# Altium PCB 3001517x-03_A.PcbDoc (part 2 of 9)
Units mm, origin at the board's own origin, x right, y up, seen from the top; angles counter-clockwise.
Board outline 100 x 72 mm, 10 copper layers (Top, GND_2, Signal_3, Signal_4, PWR_5, GND_6, Signal_7, Signal_8, GND_9, Bottom), stack 1.6 mm thick; 602 components, 497 nets, 2372 pads, 1602 vias.
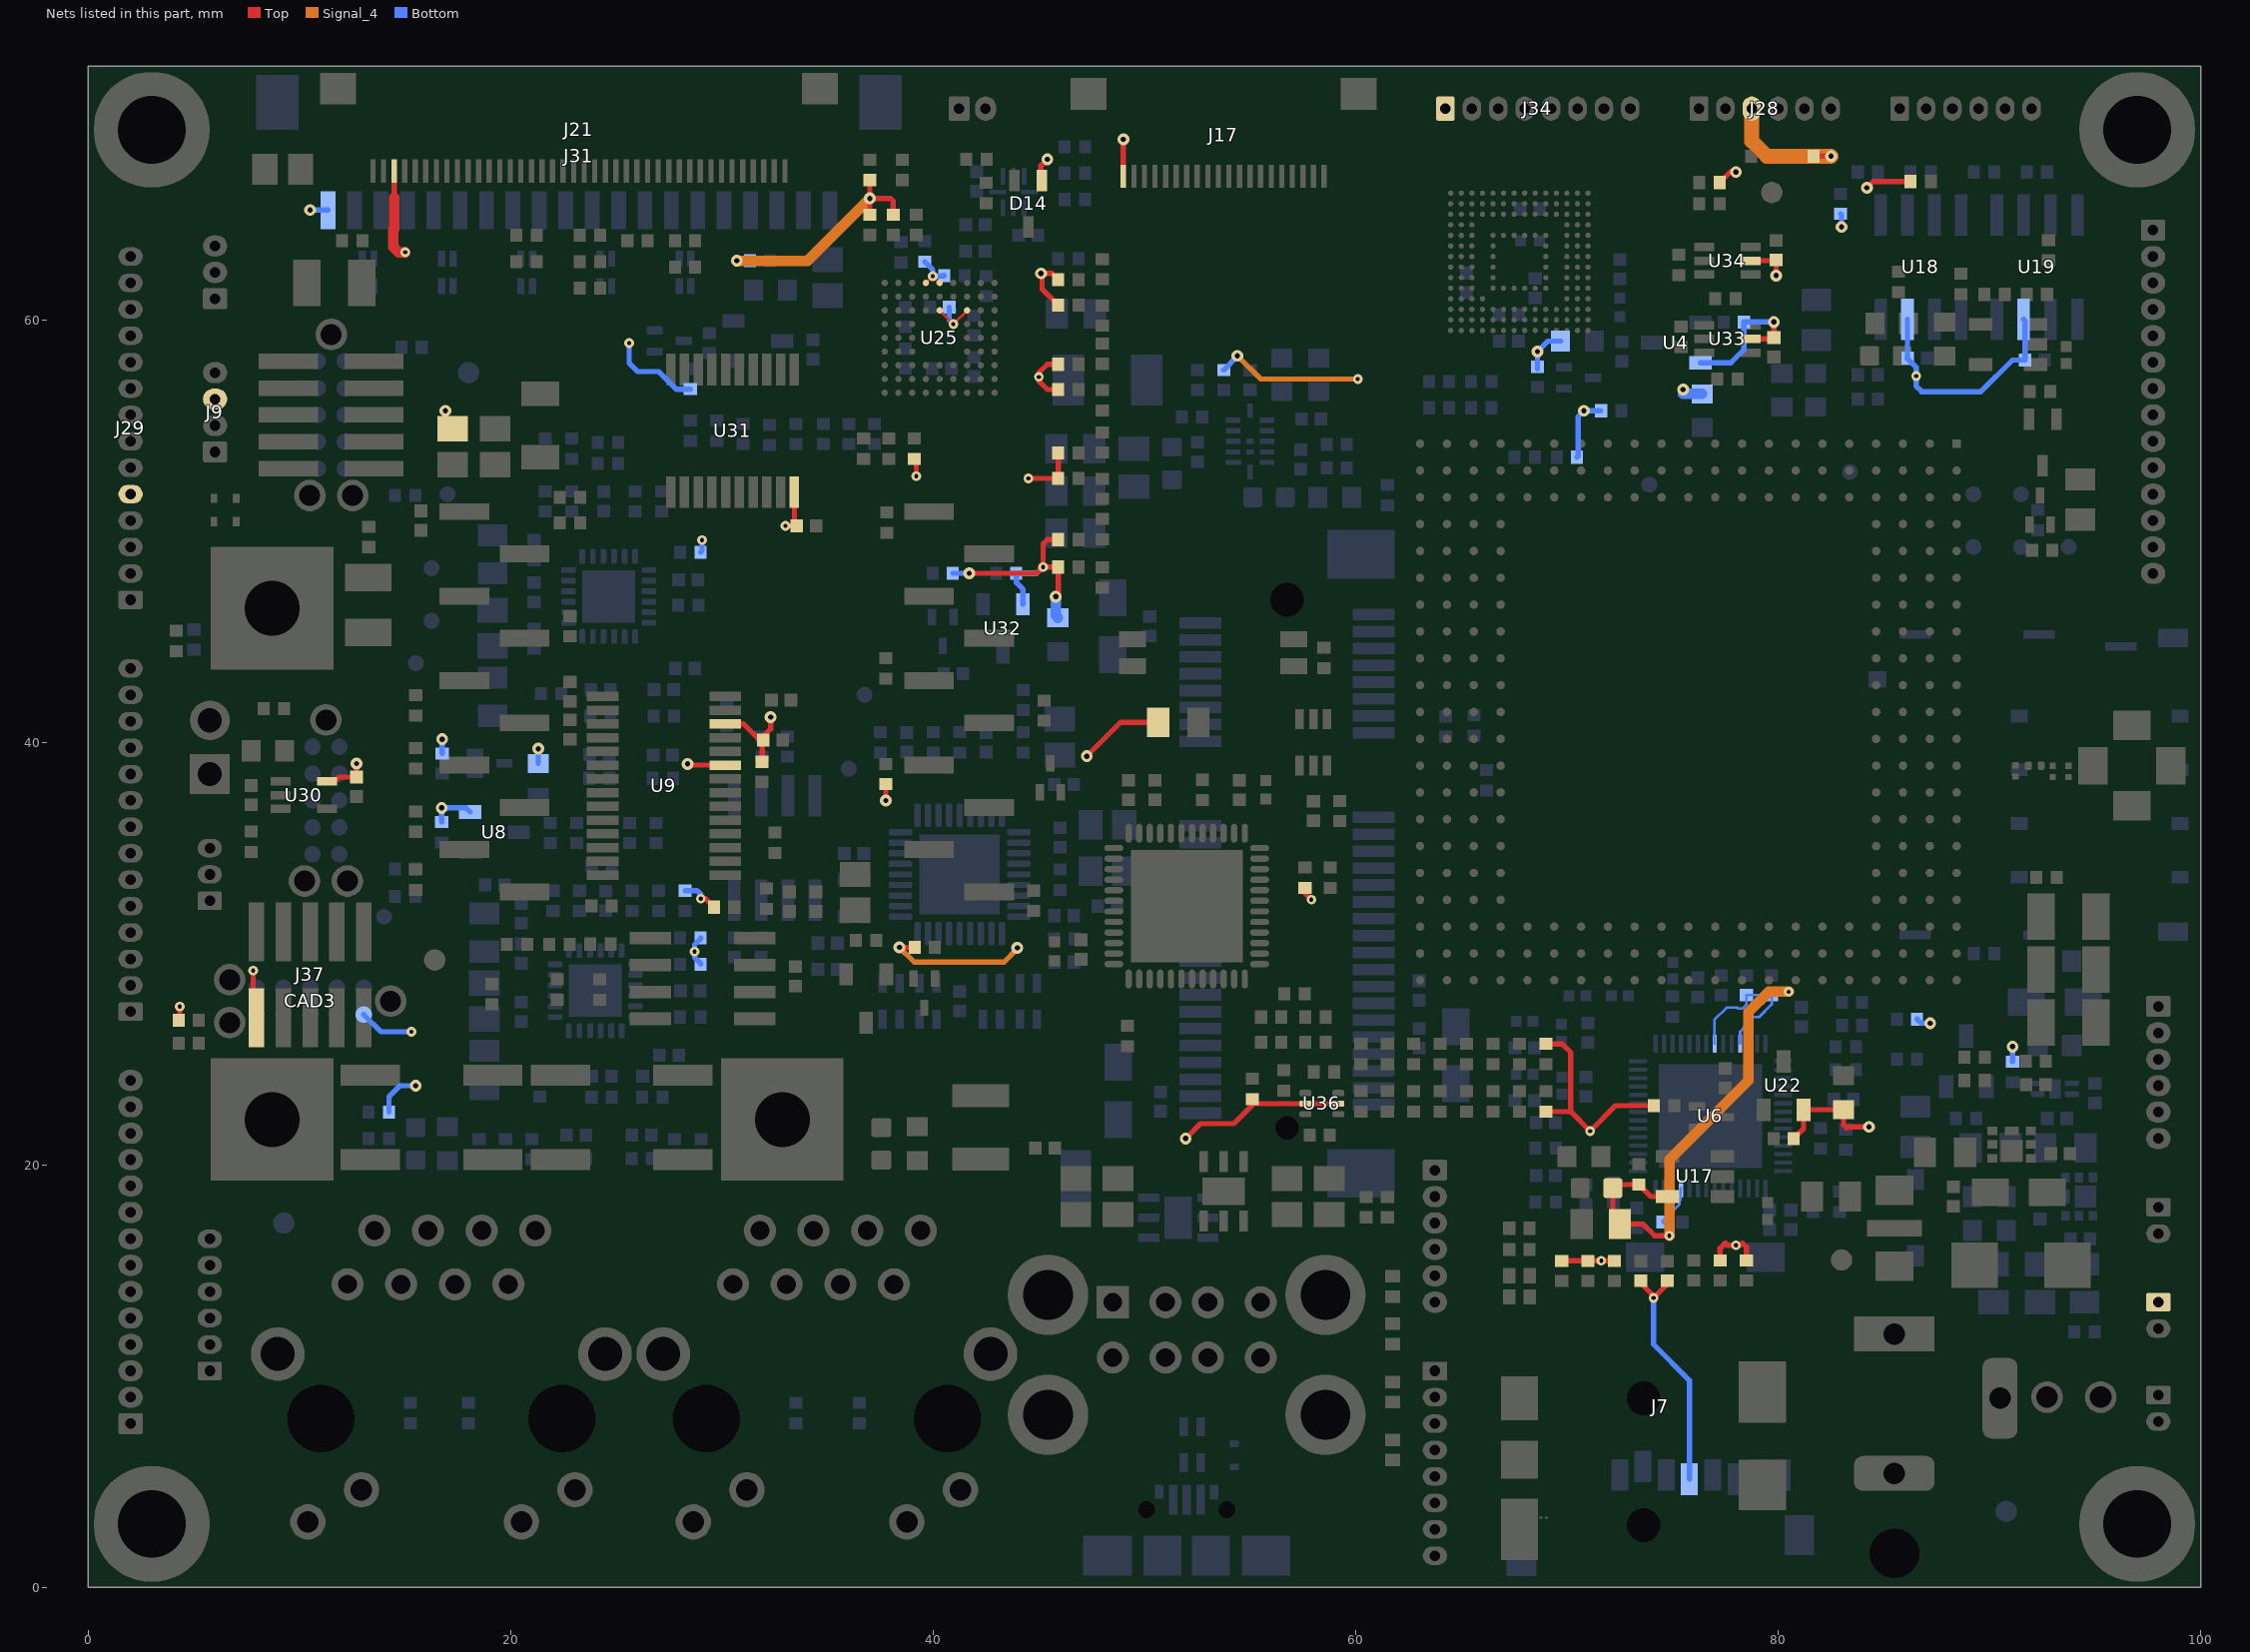
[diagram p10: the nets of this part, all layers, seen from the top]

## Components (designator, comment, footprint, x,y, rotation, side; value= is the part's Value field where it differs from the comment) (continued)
U32 "SI2323DS-T1-E3" SOT95P240X110_GSD-3N 43.299,45.389 r0 bottom
U33 "NLASB3157DFT2G" SOT65P210X110-6N 77.6,59.1 r270 top
U34 "NLASB3157DFT2G" SOT65P210X110-6N 77.6,62.8 r270 top
U35 "SI2323DS-T1-E3" SOT95P240X110_GSD-3N 31.7,59 r90 bottom
U36 "DMG1026UV-7" SOTFL50P160X60-6N 58.4,22.9 r0 top
X2 "24MHz" XTAL_C3E-3427 48.25,35 r90 bottom

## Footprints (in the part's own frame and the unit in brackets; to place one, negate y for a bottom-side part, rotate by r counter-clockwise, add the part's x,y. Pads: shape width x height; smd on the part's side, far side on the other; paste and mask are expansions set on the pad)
AMPHENOL_908-22101 [mil]
  rect 70x55 smd mask+3.94: 1(0,-72.5) 3(0,72.5)
  rect 55x70 smd mask+3.94: 2(-75,0) 4(75,0)
  Top pour cut-out: -48,-45 -48,45 48,45 48,-45
  silkscreen extent 50,-110 60,-100, body extent -85,-85 85,85, height 142
BGA72C65P9X9_700X700X112 [mm] "72-ball  BGA, 7x7mm"
  round 0.3 smd paste+0 mask+0: A1(-2.6,2.6) A2(-1.95,2.6) A3(-1.3,2.6) A4(-0.65,2.6) A5(0,2.6) A6(0.65,2.6) A7(1.3,2.6) A8(1.95,2.6) A9(2.6,2.6) B1(-2.6,1.95) B2(-1.95,1.95) B3(-1.3,1.95) B4(-0.65,1.95) B5(0,1.95) B6(0.65,1.95) B7(1.3,1.95) B8(1.95,1.95) B9(2.6,1.95) C1(-2.6,1.3) C2(-1.95,1.3) C3(-1.3,1.3) C4(-0.65,1.3) C5(0,1.3) C6(0.65,1.3) C7(1.3,1.3) C8(1.95,1.3) C9(2.6,1.3) D1(-2.6,0.65) D2(-1.95,0.65) D3(-1.3,0.65) D7(1.3,0.65) D8(1.95,0.65) D9(2.6,0.65) E1(-2.6,0) E2(-1.95,0) E3(-1.3,0) E7(1.3,0) E8(1.95,0) E9(2.6,0) F1(-2.6,-0.65) F2(-1.95,-0.65) F3(-1.3,-0.65) F7(1.3,-0.65) F8(1.95,-0.65) F9(2.6,-0.65) G1(-2.6,-1.3) G2(-1.95,-1.3) G3(-1.3,-1.3) G4(-0.65,-1.3) G5(0,-1.3) G6(0.65,-1.3) G7(1.3,-1.3) G8(1.95,-1.3) G9(2.6,-1.3) H1(-2.6,-1.95) H2(-1.95,-1.95) H3(-1.3,-1.95) H4(-0.65,-1.95) H5(0,-1.95) H6(0.65,-1.95) H7(1.3,-1.95) H8(1.95,-1.95) H9(2.6,-1.95) J1(-2.6,-2.6) J2(-1.95,-2.6) J3(-1.3,-2.6) J4(-0.65,-2.6) J5(0,-2.6) J6(0.65,-2.6) J7(1.3,-2.6) J8(1.95,-2.6) J9(2.6,-2.6)
  silkscreen extent -3.9,-3.5 3.5,3.9, body extent -3.5,-3.5 3.5,3.5, height 1.12
BGA153C50P14X14_1150X1300X100 [mm] "Sandisk eMMC"
  round 0.25 smd mask+0: A1(-3.25,3.25) A2(-2.75,3.25) A3(-2.25,3.25) A4(-1.75,3.25) A5(-1.25,3.25) A6(-0.75,3.25) A7(-0.25,3.25) A8(0.25,3.25) A9(0.75,3.25) A10(1.25,3.25) A11(1.75,3.25) A12(2.25,3.25) A13(2.75,3.25) A14(3.25,3.25) B1(-3.25,2.75) B2(-2.75,2.75) B3(-2.25,2.75) B4(-1.75,2.75) B5(-1.25,2.75) B6(-0.75,2.75) B7(-0.25,2.75) B8(0.25,2.75) B9(0.75,2.75) B10(1.25,2.75) B11(1.75,2.75) B12(2.25,2.75) B13(2.75,2.75) B14(3.25,2.75) C1(-3.25,2.25) C2(-2.75,2.25) C3(-2.25,2.25) C4(-1.75,2.25) C5(-1.25,2.25) C6(-0.75,2.25) C7(-0.25,2.25) C8(0.25,2.25) C9(0.75,2.25) C10(1.25,2.25) C11(1.75,2.25) C12(2.25,2.25) C13(2.75,2.25) C14(3.25,2.25) D1(-3.25,1.75) D2(-2.75,1.75) D3(-2.25,1.75) D4(-1.75,1.75) D12(2.25,1.75) D13(2.75,1.75) D14(3.25,1.75) E1(-3.25,1.25) E2(-2.75,1.25) E3(-2.25,1.25) E5(-1.25,1.25) E6(-0.75,1.25) E7(-0.25,1.25) E8(0.25,1.25) E9(0.75,1.25) E10(1.25,1.25) E12(2.25,1.25) E13(2.75,1.25) E14(3.25,1.25) F1(-3.25,0.75) F2(-2.75,0.75) F3(-2.25,0.75) F5(-1.25,0.75) F10(1.25,0.75) F12(2.25,0.75) F13(2.75,0.75) F14(3.25,0.75) G1(-3.25,0.25) G2(-2.75,0.25) G3(-2.25,0.25) G5(-1.25,0.25) G10(1.25,0.25) G12(2.25,0.25) G13(2.75,0.25) G14(3.25,0.25) H1(-3.25,-0.25) H2(-2.75,-0.25) H3(-2.25,-0.25) H5(-1.25,-0.25) H10(1.25,-0.25) H12(2.25,-0.25) H13(2.75,-0.25) H14(3.25,-0.25) J1(-3.25,-0.75) J2(-2.75,-0.75) J3(-2.25,-0.75) J5(-1.25,-0.75) J10(1.25,-0.75) J12(2.25,-0.75) J13(2.75,-0.75) J14(3.25,-0.75) K1(-3.25,-1.25) K2(-2.75,-1.25) K3(-2.25,-1.25) K5(-1.25,-1.25) K6(-0.75,-1.25) K7(-0.25,-1.25) K8(0.25,-1.25) K9(0.75,-1.25) K10(1.25,-1.25) K12(2.25,-1.25) K13(2.75,-1.25) K14(3.25,-1.25) L1(-3.25,-1.75) L2(-2.75,-1.75) L3(-2.25,-1.75) L12(2.25,-1.75) L13(2.75,-1.75) L14(3.25,-1.75) M1(-3.25,-2.25) M2(-2.75,-2.25) M3(-2.25,-2.25) M4(-1.75,-2.25) M5(-1.25,-2.25) M6(-0.75,-2.25) M7(-0.25,-2.25) M8(0.25,-2.25) M9(0.75,-2.25) M10(1.25,-2.25) M11(1.75,-2.25) M12(2.25,-2.25) M13(2.75,-2.25) M14(3.25,-2.25) N1(-3.25,-2.75) N2(-2.75,-2.75) N3(-2.25,-2.75) N4(-1.75,-2.75) N5(-1.25,-2.75) N6(-0.75,-2.75) N7(-0.25,-2.75) N8(0.25,-2.75) N9(0.75,-2.75) N10(1.25,-2.75) N11(1.75,-2.75) N12(2.25,-2.75) N13(2.75,-2.75) N14(3.25,-2.75) P1(-3.25,-3.25) P2(-2.75,-3.25) P3(-2.25,-3.25) P4(-1.75,-3.25) P5(-1.25,-3.25) P6(-0.75,-3.25) P7(-0.25,-3.25) P8(0.25,-3.25) P9(0.75,-3.25) P10(1.25,-3.25) P11(1.75,-3.25) P12(2.25,-3.25) P13(2.75,-3.25) P14(3.25,-3.25)
  silkscreen extent -6.3,6.1 -6.1,6.3, body extent -5.8,-6.55 5.8,6.55, height 1.01
CAPC0603X33AL [mil]
  rect 12x12 smd mask+2: 1(-10.5,0) 2(10.5,0)
  body extent -12,-6 12,6, height 13
CAPC1005X55AL [mm]
  rect 0.52x0.52 smd mask+0.051: 1(-0.44,0) 2(0.44,0)
  body extent -0.5,-0.25 0.5,0.25, height 0.55
CAPC1005X55L [mm]
  rect 0.52x0.52 smd mask+0.05: 1(-0.4,0) 2(0.4,0)
  body extent -0.5,-0.25 0.5,0.25, height 0.55
CAPC1005X55N#1 [mm]
  rect 0.6x0.62 smd: 1(-0.46,0) 2(0.46,0)
  body extent -0.5,-0.25 0.5,0.25, height 0.55
CAPC1005X55N#2 [mm]
  rect 0.6x0.62 smd mask+0.05: 1(-0.46,0) 2(0.46,0)
  body extent -0.5,-0.25 0.5,0.25, height 0.55
CAPC1608X90N#1 [mm] "0603"
  rect 0.95x1 smd: 1(-0.8,0) 2(0.8,0)
  body extent -0.87,-0.47 0.87,0.47, height 0.9
CAPC1608X90N#2 [mm] "0603"
  rrect22% 0.89x0.93 smd: 1(-0.77,0) 2(0.77,0)
  body extent -0.8,-0.4 0.8,0.4, height 0.9
CAPC2013X135N [mm] "0805, 1.35mm max height"
  rect 1.05x1.4 smd: 1(-0.9,0) 2(0.9,0)
  body extent -1.1,-0.72 1.1,0.72, height 1.35
CAPC2013X145N [mm] "0805, 1.45mm max height"
  rect 1.15x1.45 smd: 1(-0.9,0) 2(0.9,0)
  body extent -1.1,-0.72 1.1,0.72, height 1.45
CAPC3216X190N [mm]
  rect 1.15x1.8 smd: 1(-1.5,0) 2(1.5,0)
  body extent -1.7,-0.9 1.7,0.9, height 1.9
CAPMP3216X120N [mm]
  rect 1.75x1.3 smd: 1(-1.35,0) 2(1.35,0)
  body extent -1.7,-0.9 1.7,0.9, height 1.21
CC6UL_LGA [mm]
  rect 0.4x0.4 smd paste-0.4: A1(-12.64,12.7)
  round 0.4 smd paste+0.3 mask+0.05: A2(-11.37,12.7) A3(-10.1,12.7) A4(-8.83,12.7) A5(-7.56,12.7) A6(-6.29,12.7) A7(-5.02,12.7) A8(-3.75,12.7) A9(-2.48,12.7) A10(-1.21,12.7) A11(0.06,12.7) A12(1.33,12.7) A13(2.6,12.7) A14(3.87,12.7) A15(5.14,12.7) A16(6.41,12.7) A17(7.68,12.7) A18(8.95,12.7) A19(10.22,12.7) A20(11.49,12.7) A21(12.76,12.7) AA1(-12.64,-12.7) AA2(-11.37,-12.7) AA3(-10.1,-12.7) AA4(-8.83,-12.7) AA5(-7.56,-12.7) AA6(-6.29,-12.7) AA7(-5.02,-12.7) AA8(-3.75,-12.7) AA9(-2.48,-12.7) AA10(-1.21,-12.7) AA11(0.06,-12.7) AA12(1.33,-12.7) AA13(2.6,-12.7) AA14(3.87,-12.7) AA15(5.14,-12.7) AA16(6.41,-12.7) AA17(7.68,-12.7) AA18(8.95,-12.7) AA19(10.22,-12.7) AA20(11.49,-12.7) AA21(12.76,-12.7) B1(-12.64,11.43) B2(-11.37,11.43) B3(-10.1,11.43) B4(-8.83,11.43) B5(-7.56,11.43) B6(-6.29,11.43) B7(-5.02,11.43) B8(-3.75,11.43) B9(-2.48,11.43) B10(-1.21,11.43) B11(0.06,11.43) B12(1.33,11.43) B13(2.6,11.43) B14(3.87,11.43) B15(5.14,11.43) B16(6.41,11.43) B17(7.68,11.43) B18(8.95,11.43) B19(10.22,11.43) B20(11.49,11.43) B21(12.76,11.43) C1(-12.64,10.16) C2(-11.37,10.16) C3(-10.1,10.16) C4(-8.83,10.16) C5(-7.56,10.16) C6(-6.29,10.16) C7(-5.02,10.16) C8(-3.75,10.16) C9(-2.48,10.16) C10(-1.21,10.16) C11(0.06,10.16) C12(1.33,10.16) C13(2.6,10.16) C14(3.87,10.16) C15(5.14,10.16) C16(6.41,10.16) C17(7.68,10.16) C18(8.95,10.16) C19(10.22,10.16) C20(11.49,10.16) C21(12.76,10.16) D1(-12.64,8.89) D2(-11.37,8.89) D3(-10.1,8.89) D4(-8.83,8.89) D5(-7.56,8.89) D6(-6.29,8.89) D7(-5.02,8.89) D8(-3.75,8.89) D9(-2.48,8.89) D10(-1.21,8.89) D11(0.06,8.89) D12(1.33,8.89) D13(2.6,8.89) D14(3.87,8.89) D15(5.14,8.89) D16(6.41,8.89) D17(7.68,8.89) D18(8.95,8.89) D19(10.22,8.89) D20(11.49,8.89) D21(12.76,8.89) E1(-12.64,7.62) E2(-11.37,7.62) E3(-10.1,7.62) E19(10.22,7.62) E20(11.49,7.62) E21(12.76,7.62) F1(-12.64,6.35) F2(-11.37,6.35) F3(-10.1,6.35) F19(10.22,6.35) F20(11.49,6.35) F21(12.76,6.35) G1(-12.64,5.08) G2(-11.37,5.08) G3(-10.1,5.08) G19(10.22,5.08) G20(11.49,5.08) G21(12.76,5.08) H1(-12.64,3.81) H2(-11.37,3.81) H3(-10.1,3.81) H19(10.22,3.81) H20(11.49,3.81) H21(12.76,3.81) J1(-12.64,2.54) J2(-11.37,2.54) J3(-10.1,2.54) J19(10.22,2.54) J20(11.49,2.54) J21(12.76,2.54) K1(-12.64,1.27) K2(-11.37,1.27) K3(-10.1,1.27) K19(10.22,1.27) K20(11.49,1.27) K21(12.76,1.27) L1(-12.64,0) L2(-11.37,0) L3(-10.1,0) L19(10.22,0) L20(11.49,0) L21(12.76,0) M1(-12.64,-1.27) M2(-11.37,-1.27) M3(-10.1,-1.27) M19(10.22,-1.27) M20(11.49,-1.27) M21(12.76,-1.27) N1(-12.64,-2.54) N2(-11.37,-2.54) N3(-10.1,-2.54) N19(10.22,-2.54) N20(11.49,-2.54) N21(12.76,-2.54) P1(-12.64,-3.81) P2(-11.37,-3.81) P3(-10.1,-3.81) P19(10.22,-3.81) P20(11.49,-3.81) P21(12.76,-3.81) R1(-12.64,-5.08) R2(-11.37,-5.08) R3(-10.1,-5.08) R19(10.22,-5.08) R20(11.49,-5.08) R21(12.76,-5.08) T1(-12.64,-6.35) T2(-11.37,-6.35) T3(-10.1,-6.35) T19(10.22,-6.35) T20(11.49,-6.35) T21(12.76,-6.35) U1(-12.64,-7.62) U2(-11.37,-7.62) U3(-10.1,-7.62) U19(10.22,-7.62) U20(11.49,-7.62) U21(12.76,-7.62) V1(-12.64,-8.89) V2(-11.37,-8.89) V3(-10.1,-8.89) V4(-8.83,-8.89) V5(-7.56,-8.89) V6(-6.29,-8.89) V7(-5.02,-8.89) V8(-3.75,-8.89) V9(-2.48,-8.89) V10(-1.21,-8.89) V11(0.06,-8.89) V12(1.33,-8.89) V13(2.6,-8.89) V14(3.87,-8.89) V15(5.14,-8.89) V16(6.41,-8.89) V17(7.68,-8.89) V18(8.95,-8.89) V19(10.22,-8.89) V20(11.49,-8.89) V21(12.76,-8.89) W1(-12.64,-10.16) W2(-11.37,-10.16) W3(-10.1,-10.16) W4(-8.83,-10.16) W5(-7.56,-10.16) W6(-6.29,-10.16) W7(-5.02,-10.16) W8(-3.75,-10.16) W9(-2.48,-10.16) W10(-1.21,-10.16) W11(0.06,-10.16) W12(1.33,-10.16) W13(2.6,-10.16) W14(3.87,-10.16) W15(5.14,-10.16) W16(6.41,-10.16) W17(7.68,-10.16) W18(8.95,-10.16) W19(10.22,-10.16) W20(11.49,-10.16) W21(12.76,-10.16) Y1(-12.64,-11.43) Y2(-11.37,-11.43) Y3(-10.1,-11.43) Y4(-8.83,-11.43) Y5(-7.56,-11.43) Y6(-6.29,-11.43) Y7(-5.02,-11.43) Y8(-3.75,-11.43) Y9(-2.48,-11.43) Y10(-1.21,-11.43) Y11(0.06,-11.43) Y12(1.33,-11.43) Y13(2.6,-11.43) Y14(3.87,-11.43) Y15(5.14,-11.43) Y16(6.41,-11.43) Y17(7.68,-11.43) Y18(8.95,-11.43) Y19(10.22,-11.43) Y20(11.49,-11.43) Y21(12.76,-11.43)
  body extent -14.44,-14.5 14.56,17.36, height 4.35
conn_CSCD443CCS011B00G [mil] "Bobbintron : CSCD443CCS011B00G"
  rect 65x150 hole 40 slot 126 at 90 deg: 1(0,0)
  rrect50% 65x150 / inner rect 65x150 / far side rrect50% 65x150 hole 40 slot 126 at 90 deg: 2(-260,0)
  rrect50% 150x65 / inner rect 150x65 / far side rrect50% 150x65 hole 40 slot 126 at 0 deg: 3(-120,-197.01)
  round 0 hole 93 unplated: 4(-409,0)
  body extent -571,-207 20,177, height 433
CUI_SJ1-3515-SMT [mm]
  rect 2.9x1.75 smd: 1(-3.25,5.75)
  rect 2.9x2.25 smd: 2(3.25,-5.75)
  rect 2.1x1.75 smd: 3(2.95,5.75)
  rect 2.4x2.25 smd: 4(-1.15,-5.75)
  rect 1.8x1.75 smd: 5(0.05,5.75)
  round 0 hole 1.6 unplated: MT1(-3.05,-0.125) MT2(2.95,-0.125)
  body extent -9.05,-6.12 5.95,5.88, height 5
DFN200X200X80-6N [mm]
  rect 0.47x0.4 smd mask+0.05: 1(-0.91,0.65) 2(-0.91,0) 3(-0.91,-0.65) 4(0.91,-0.65) 5(0.91,0) 6(0.91,0.65)
  rect 1.05x1 smd mask+0: 7(0,0.3)
  rect 0.66x0.4 smd mask+0.05: 8(0,-0.65)
  silkscreen extent -0.87,-1.62 -0.63,-1.38, body extent -1,-1 1,1, height 0.8
DIOM5436X244N [mm]
  rect 2.2x2.15 smd: A(-2.2,0) K(2.2,0)
  body extent -2.8,-1.97 2.8,1.97, height 2.44
FCI_68002-102HLF [mil]
  rect 74x74 hole 45: 1(0,0)
  round 74 hole 45: 2(100,0)
  body extent -51,-46 149,49, height 330
fiducial_40mil_round [mil]
  round 40 smd paste-40 mask+20: 1(0,0)
  Top pour cut-out: -40,0 -36.96,15.31 -28.28,28.28 -15.31,36.96 0,40 0,40 15.31,36.96 28.28,28.28 36.96,15.31 40,0 40,0 36.96,-15.31 28.28,-28.28 15.31,-36.96 0,-40 0,-40 -15.31,-36.96 -28.28,-28.28 -36.96,-15.31 -40,0
FIL_DLP11S [mm]
  rect 0.75x0.35 smd: 1(-0.65,-0.275) 2(0.65,-0.275) 3(0.65,0.275) 4(-0.65,0.275)
  silkscreen extent -0.88,-1.15 -0.73,-1, body extent -0.67,-0.55 0.68,0.55, height 0.92
FIL_DLW21H [mm]
  rect 0.9x0.4 smd: 1(-0.85,-0.4) 2(0.85,-0.4) 3(0.85,0.4) 4(-0.85,0.4)
  body extent -1.1,-0.7 1.1,0.7, height 1
FIL_ELKEA [mm]
  rect 1.4x1.8 smd: 1(-1.8,0) 3(1.8,0)
  rect 0.8x2.6 smd: 2(0,0)
  body extent -1.6,-0.9 1.6,0.9, height 2.2
FOXCONN_AS0B221-S68Q-7H [mm]
  rect 0.55x2 smd: 1(0.7,-4.1) 2(1.1,4.1) 3(1.5,-4.1) 4(1.9,4.1) 5(2.3,-4.1) 6(2.7,4.1) 7(3.1,-4.1) 8(3.5,4.1) 9(3.9,-4.1) 10(4.3,4.1) 11(4.7,-4.1) 12(5.1,4.1) 13(5.5,-4.1) 14(5.9,4.1) 15(6.3,-4.1) 16(6.7,4.1) 17(10.3,-4.1) 18(10.7,4.1) 19(11.1,-4.1) 20(11.5,4.1) 21(11.9,-4.1) 22(12.3,4.1) 23(12.7,-4.1) 24(13.1,4.1) 25(13.5,-4.1) 26(13.9,4.1) 27(14.3,-4.1) 28(14.7,4.1) 29(15.1,-4.1) 30(15.5,4.1) 31(15.9,-4.1) 32(16.3,4.1) 33(16.7,-4.1) 34(17.1,4.1) 35(17.5,-4.1) 36(17.9,4.1) 37(18.3,-4.1) 38(18.7,4.1) 39(19.1,-4.1) 40(19.5,4.1) 41(19.9,-4.1) 42(20.3,4.1) 43(20.7,-4.1) 44(21.1,4.1) 45(21.5,-4.1) 46(21.9,4.1) 47(22.3,-4.1) 48(22.7,4.1) 49(23.1,-4.1) 50(23.5,4.1) 51(23.9,-4.1) 52(24.3,4.1)
  round 0 hole 1.6 unplated: H1(0,0)
  round 0 hole 1.1 unplated: H2(25,0)
  rect 2.3x3.2 smd: MT1(-2.15,-3.5) MT2(27.15,-3.5)
  body extent -2.4,-4.75 27.4,4.75, height 6.8
HIROSE_DF14A-20P-1.25H [mm]
  rect 0.7x1.8 smd: 1(11.875,-2.55) 2(10.625,-2.55) 3(9.375,-2.55) 4(8.125,-2.55) 5(6.875,-2.55) 6(5.625,-2.55) 7(4.375,-2.55) 8(3.125,-2.55) 9(1.875,-2.55) 10(0.625,-2.55) 11(-0.625,-2.55) 12(-1.875,-2.55) 13(-3.125,-2.55) 14(-4.375,-2.55) 15(-5.625,-2.55) 16(-6.875,-2.55) 17(-8.125,-2.55) 18(-9.375,-2.55) 19(-10.625,-2.55) 20(-11.875,-2.55)
  rect 2x2.6 smd: MT1(14.275,2.55) MT21(-14.275,2.55)
  body extent -14.97,-3.02 14.98,3.68, height 2.49
INDC0603X33N [mm]
  rrect48% 0.33x0.4 smd: 1(-0.3,0) 2(0.3,0)
  silkscreen extent -0.3,-0.38 0.3,0.38, body extent -0.3,-0.15 0.3,0.15, height 0.33
INDC1005X60N [mm]
  rect 0.59x0.72 smd: 1(-0.48,0) 2(0.48,0)
  body extent -0.55,-0.35 0.55,0.35, height 0.6
INDC2013X110N [mm]
  rect 1.2x1.45 smd: 1(-0.85,0) 2(0.85,0)
  body extent -1.1,-0.72 1.1,0.72, height 1.1
INDM_SRP4020TA [mm]
  rect 1.5x2.4 smd: 1(-1.85,0) 2(1.85,0)
  body extent -2.2,-2.1 2.2,2.1, height 1.91
KYCON_KMMX-ABSMT5 [mm]
  rect 0.4x0.7 smd mask+0.058: 1(-1.3,3)
  rect 0.4x1.4 smd: 2(-0.65,2.65) 3(0,2.65) 4(0.65,2.65)
  rect 0.4x0.65 smd mask+0.058: 5(1.3,3.025)
  rect 2.3x1.9 smd: 6(-3.75,0) 9(3.75,0)
  rect 1.8x1.9 smd: 7(-1.15,0) 8(1.15,0)
  round 0 hole 0.813 unplated: 10(-1.9,2.18) 11(1.9,2.18)
  Top region: 1.1,2.7 1.1,1.95 1.275,1.95 1.275,2.18 1.278,2.235 1.28,2.258 1.282,2.278 1.285,2.29 1.288,2.305 1.29,2.315 1.292,2.328 1.3,2.355 1.308,2.378 1.315,2.4 1.32,2.412 1.335,2.448 1.34,2.458 1.342,2.462 1.345,2.468 1.358,2.49 1.372,2.515 1.388,2.538 1.4,2.555 1.418,2.578 1.435,2.598 1.482,2.645 1.5,2.66 1.5,2.7
  Top region: -1.1,2.7 -1.1,1.95 -1.275,1.95 -1.275,2.18 -1.278,2.235 -1.28,2.258 -1.282,2.278 -1.285,2.29 -1.288,2.305 -1.29,2.315 -1.292,2.328 -1.3,2.355 -1.308,2.378 -1.315,2.4 -1.32,2.412 -1.335,2.448 -1.34,2.458 -1.342,2.462 -1.345,2.468 -1.358,2.49 -1.372,2.515 -1.388,2.538 -1.4,2.555 -1.418,2.578 -1.435,2.598 -1.482,2.645 -1.5,2.66 -1.5,2.7
  body extent -4.4,-2.72 4.4,2.88, height 2.78
KYCON_KUSBX-AS2N [mil]
  rect 60x60 hole 35: A1(0,0)
  round 60 hole 35: A2(98.43,0) A3(177.17,0) A4(275.59,0) B1(0,-103.15) B2(98.43,-103.15) B3(177.17,-103.15) B4(275.59,-103.15)
  round 150 hole 93: SH1(-120.87,-209.84) SH2(-120.87,13.78) SH3(396.46,-209.84) SH4(396.46,13.78)
  body extent -171,-633 446,56, height 634
LABEL_10x10 [mm]
  silkscreen extent -5.08,-5.08 5.08,5.08
LEDM3020X130N [mm]
  rect 1.3x2.2 smd: A(-1.3,0) K(1.3,0)
  body extent -1.6,-1.1 1.6,1.1, height 1.5
MH_185_125_NP [mm]
  round 3.175 hole 3.175 unplated: 1(0,0)
  Keep-Out Layer circle w0.102: c0,0 r2.349
MOLEX_53047-0210#1 [mm]
  rrect20% 0.875x1.15 hole 0.5: 1(0,0)
  oval 0.875x1.15 hole 0.5: 2(1.25,0)
  body extent -1.52,-1.15 2.73,2.05, height 4.2
MOLEX_53047-0210#2 [mm]
  rrect20% 1x1.15 hole 0.5: 1(0,0)
  oval 1x1.15 hole 0.5: 2(1.25,0)
  body extent -1.52,-1.15 2.73,2.05, height 4.2
MOLEX_53047-0310#1 [mm]
  rrect20% 1x1.15 hole 0.5: 1(0,0)
  oval 1x1.15 hole 0.5: 2(1.25,0) 3(2.5,0)
  body extent -1.5,-1.15 4,2.05, height 4.2
MOLEX_53047-0310#2 [mm]
  rrect20% 0.875x1.15 hole 0.5: 1(0,0)
  oval 0.875x1.15 hole 0.5: 2(1.25,0) 3(2.5,0)
  body extent -1.5,-1.15 4,2.05, height 4.2
MOLEX_53047-0410 [mm]
  rrect20% 1x1.15 hole 0.5: 1(0,0)
  oval 1x1.15 hole 0.5: 2(1.25,0) 3(2.5,0) 4(3.75,0)
  body extent -1.52,-1.15 5.23,2.05, height 4.2
MOLEX_53047-0610#1 [mm]
  rrect20% 1x1.15 hole 0.5: 1(0,0)
  oval 1x1.15 hole 0.5: 2(1.25,0) 3(2.5,0) 4(3.75,0) 5(5,0) 6(6.25,0)
  body extent -1.5,-1.15 7.75,2.05, height 4.2
MOLEX_53047-0610#2 [mm]
  rrect20% 0.875x1.15 hole 0.5: 1(0,0)
  oval 0.875x1.15 hole 0.5: 2(1.25,0) 3(2.5,0) 4(3.75,0) 5(5,0) 6(6.25,0)
  body extent -1.5,-1.15 7.75,2.05, height 4.2
MOLEX_53047-0610#3 [mm]
  rrect20% 1x1.15 / inner round 0.76 / far side rrect20% 1x1.15 hole 0.5: 1(0,0)
  oval 1x1.15 / inner round 0.76 / far side oval 1x1.15 hole 0.5: 2(1.25,0)
  oval 1x1.15 hole 0.5: 3(2.5,0) 4(3.75,0) 5(5,0) 6(6.25,0)
  body extent -1.5,-1.15 7.75,2.05, height 4.2
MOLEX_53047-0810#1 [mm]
  rect 0.875x1.15 / inner rect 0.76x0.76 / far side rect 0.875x1.15 hole 0.5: 1(0,0)
  oval 0.875x1.15 / inner round 0.76 / far side oval 0.875x1.15 hole 0.5: 2(1.25,0) 3(2.5,0) 4(3.75,0) 5(5,0) 6(6.25,0) 7(7.5,0) 8(8.75,0)
  body extent -1.5,-1.15 10.25,2.05, height 4.2
MOLEX_53047-0810#2 [mm]
  rrect20% 0.875x1.15 hole 0.5: 1(0,0)
  oval 0.875x1.15 hole 0.5: 2(1.25,0) 3(2.5,0) 4(3.75,0) 5(5,0) 6(6.25,0) 7(7.5,0) 8(8.75,0)
  body extent -1.5,-1.15 10.25,2.05, height 4.2
MOLEX_53047-1410#1 [mm]
  rrect20% 1x1.15 hole 0.5: 1(0,0)
  oval 1x1.15 hole 0.5: 2(1.25,0) 3(2.5,0) 4(3.75,0) 5(5,0) 6(6.25,0) 7(7.5,0) 8(8.75,0) 9(10,0) 10(11.25,0) 11(12.5,0) 12(13.75,0) 13(15,0) 14(16.25,0)
  body extent -1.5,-1.15 17.75,2.05, height 4.2
MOLEX_53047-1410#2 [mm]
  rrect20% 0.875x1.15 hole 0.5: 1(0,0)
  oval 0.875x1.15 hole 0.5: 2(1.25,0) 3(2.5,0) 4(3.75,0) 5(5,0) 6(6.25,0) 7(7.5,0) 8(8.75,0) 9(10,0) 10(11.25,0) 11(12.5,0) 12(13.75,0) 13(15,0) 14(16.25,0)
  body extent -1.5,-1.15 17.75,2.05, height 4.2
MOLEX_78727-0001 [mm]
  rect 0.8x0.6 smd: 1(0.33,4.38) 2(0.33,1.84) 3(0.33,-0.7) 4(0.33,-3.24) 5(-7.29,4.38) 6(-7.29,1.84) 7(-7.29,-0.7) 8(-7.29,-3.24)
  rect 0.85x0.8 smd: 9(-13.99,-4.98)
  rect 1.5x0.42 smd: 10(-2.47,-6.54) 12(-6.35,7.11) 13(-12.21,7.11) 14(-12.21,-7.11) 15(-6.35,-7.11)
  rect 1.4x0.87 smd: 11(0,6.95) 16(0,-6.95)
  body extent -14.53,-7.26 0.69,7.27, height 1.4
MOLEX_500873-0806 [mm]
  rect 0.8x1.5 smd: 1(0,0) 2(1.1,-0.4) 3(2.2,0) 4(3.3,0.2) 5(4.4,0) 6(5.5,0.2) 7(6.6,0) 8(7.7,0)
  rect 1.8x1.4 smd: 9(1.2,-10.3) 10(6.9,-10.3)
  rect 1.4x1.9 smd: 11(8.5,2.85) 12(-4.65,3.85)
  body extent -5.05,-10.7 8.95,4.5, height 1.87
NET_TIE_4mil [mil] "Net Tie for 4mil traces"
  rect 5x4 smd paste-5 mask-5: 1(-5,0) 2(5,0)
  Top region: -3,-2 3,-2 3,2 -3,2
NXP_XQFN8 [mm] "Quad Flat No-Lead (QFN), 0.50 mm pitch; square, 3 pin X 1 pin, 1.60 mm L X 1.60 mm W X 0.50 mm H body"
  rrect55% 0.81x0.22 smd mask+0.05: 1(-0.75,0.5) 2(-0.75,0) 3(-0.75,-0.5) 5(0.75,-0.5) 6(0.75,0) 7(0.75,0.5)
  rrect55% 0.22x0.81 smd mask+0.05: 4(0,-0.75) 8(0,0.75)
  Top keep-out region: -0.2,0.2 0.2,0.2 0.2,-0.2 -0.2,-0.2
  silkscreen extent -1.65,0.7 -1.45,0.9, body extent -0.85,-0.85 0.85,0.85, height 0.5
omron_xf2m-2015-1a [mm]
  rect 0.25x1.1 smd: 1(-4.75,1.95) 2(-4.25,1.95) 3(-3.75,1.95) 4(-3.25,1.95) 5(-2.75,1.95) 6(-2.25,1.95) 7(-1.75,1.95) 8(-1.25,1.95) 9(-0.75,1.95) 10(-0.25,1.95) 11(0.25,1.95) 12(0.75,1.95) 13(1.25,1.95) 14(1.75,1.95) 15(2.25,1.95) 16(2.75,1.95) 17(3.25,1.95) 18(3.75,1.95) 19(4.25,1.95) 20(4.75,1.95)
  rect 1.7x1.5 smd: M1(6.4,-1.95) M2(-6.4,-1.95)
  body extent -7.05,-2.9 7.05,3.3, height 2.18
OMRON_XF2M-4015-1A [mm]
  rect 0.25x1.1 smd: 1(-9.75,1.95) 2(-9.25,1.95) 3(-8.75,1.95) 4(-8.25,1.95) 5(-7.75,1.95) 6(-7.25,1.95) 7(-6.75,1.95) 8(-6.25,1.95) 9(-5.75,1.95) 10(-5.25,1.95) 11(-4.75,1.95) 12(-4.25,1.95) 13(-3.75,1.95) 14(-3.25,1.95) 15(-2.75,1.95) 16(-2.25,1.95) 17(-1.75,1.95) 18(-1.25,1.95) 19(-0.75,1.95) 20(-0.25,1.95) 21(0.25,1.95) 22(0.75,1.95) 23(1.25,1.95) 24(1.75,1.95) 25(2.25,1.95) 26(2.75,1.95) 27(3.25,1.95) 28(3.75,1.95) 29(4.25,1.95) 30(4.75,1.95) 31(5.25,1.95) 32(5.75,1.95) 33(6.25,1.95) 34(6.75,1.95) 35(7.25,1.95) 36(7.75,1.95) 37(8.25,1.95) 38(8.75,1.95) 39(9.25,1.95) 40(9.75,1.95)
  rect 1.7x1.5 smd: M1(11.4,-1.95) M2(-11.4,-1.95)
  body extent -12.05,-2.9 12.05,3.3, height 2.18
QFN40P700X700X80-57T560X560N [mm] "Quad Flat No-Lead (QFN with Tab), 0.40 mm pitch; square, 14 pin X 14 pin, 7.00 mm L X 7.00 mm W X 0.80 mm H body"
  rrect50% 0.86x0.2 smd mask+0.05: 1(-3.43,2.6) 2(-3.43,2.2) 3(-3.43,1.8) 4(-3.43,1.4) 5(-3.43,1) 6(-3.43,0.6) 7(-3.43,0.2) 8(-3.43,-0.2) 9(-3.43,-0.6) 10(-3.43,-1) 11(-3.43,-1.4) 12(-3.43,-1.8) 13(-3.43,-2.2) 14(-3.43,-2.6) 29(3.43,-2.6) 30(3.43,-2.2) 31(3.43,-1.8) 32(3.43,-1.4) 33(3.43,-1) 34(3.43,-0.6) 35(3.43,-0.2) 36(3.43,0.2) 37(3.43,0.6) 38(3.43,1) 39(3.43,1.4) 40(3.43,1.8) 41(3.43,2.2) 42(3.43,2.6)
  rrect50% 0.2x0.86 smd mask+0.05: 15(-2.6,-3.43) 16(-2.2,-3.43) 17(-1.8,-3.43) 18(-1.4,-3.43) 19(-1,-3.43) 20(-0.6,-3.43) 21(-0.2,-3.43) 22(0.2,-3.43) 23(0.6,-3.43) 24(1,-3.43) 25(1.4,-3.43) 26(1.8,-3.43) 27(2.2,-3.43) 28(2.6,-3.43) 43(2.6,3.43) 44(2.2,3.43) 45(1.8,3.43) 46(1.4,3.43) 47(1,3.43) 48(0.6,3.43) 49(0.2,3.43) 50(-0.2,3.43) 51(-0.6,3.43) 52(-1,3.43) 53(-1.4,3.43) 54(-1.8,3.43) 55(-2.2,3.43) 56(-2.6,3.43)
  rect 4.9x4.9 smd paste-4.9 mask+0: 57(0,0)
  Top region: -2.8,-2.8 -2.8,2.45 -2.45,2.8 2.8,2.8 2.8,-2.8 -2.8,-2.8
  silkscreen extent -4.04,3.08 -3.84,3.27, body extent -3.55,-3.55 3.55,3.55, height 0.8
QFN50P400X400X100-25 [mm]
  rrect50% 0.69x0.28 smd: 1(-1.9,1.25) 2(-1.9,0.75) 3(-1.9,0.25) 4(-1.9,-0.25) 5(-1.9,-0.75) 6(-1.9,-1.25) 13(1.9,-1.25) 14(1.9,-0.75) 15(1.9,-0.25) 16(1.9,0.25) 17(1.9,0.75) 18(1.9,1.25)
  rrect50% 0.28x0.69 smd: 7(-1.25,-1.9) 8(-0.75,-1.9) 9(-0.25,-1.9) 10(0.25,-1.9) 11(0.75,-1.9) 12(1.25,-1.9) 19(1.25,1.9) 20(0.75,1.9) 21(0.25,1.9) 22(-0.25,1.9) 23(-0.75,1.9) 24(-1.25,1.9)
  rect 2.5x2.5 smd: 25(0,0)
  silkscreen extent -2.59,1.66 -2.41,1.84, body extent -2.07,-2.07 2.07,2.07, height 1.01
QFN50P600X600X100-37AN [mm]
  rrect50% 1.1x0.3 smd mask+0.05: 1(-2.8,2) 2(-2.8,1.5) 3(-2.8,1) 4(-2.8,0.5) 5(-2.8,0) 6(-2.8,-0.5) 7(-2.8,-1) 8(-2.8,-1.5) 9(-2.8,-2) 19(2.8,-2) 20(2.8,-1.5) 21(2.8,-1) 22(2.8,-0.5) 23(2.8,0) 24(2.8,0.5) 25(2.8,1) 26(2.8,1.5) 27(2.8,2)
  rrect50% 0.3x1.1 smd mask+0.05: 10(-2,-2.8) 11(-1.5,-2.8) 12(-1,-2.8) 13(-0.5,-2.8) 14(0,-2.8) 15(0.5,-2.8) 16(1,-2.8) 17(1.5,-2.8) 18(2,-2.8) 28(2,2.8) 29(1.5,2.8) 30(1,2.8) 31(0.5,2.8) 32(0,2.8) 33(-0.5,2.8) 34(-1,2.8) 35(-1.5,2.8) 36(-2,2.8)
  rect 3.8x3.8 smd: 37(0,0)
  silkscreen extent -4.1,1.9 -3.8,2.2, body extent -3.05,-3.05 3.05,3.05, height 1.01
QFN50P700X700X100-49N [mm]
  oval 0.9x0.3 smd mask+0.05: 1(-3.45,2.75) 2(-3.45,2.25) 3(-3.45,1.75) 4(-3.45,1.25) 5(-3.45,0.75) 6(-3.45,0.25) 7(-3.45,-0.25) 8(-3.45,-0.75) 9(-3.45,-1.25) 10(-3.45,-1.75) 11(-3.45,-2.25) 12(-3.45,-2.75) 25(3.45,-2.75) 26(3.45,-2.25) 27(3.45,-1.75) 28(3.45,-1.25) 29(3.45,-0.75) 30(3.45,-0.25) 31(3.45,0.25) 32(3.45,0.75) 33(3.45,1.25) 34(3.45,1.75) 35(3.45,2.25) 36(3.45,2.75)
  oval 0.3x0.9 smd mask+0.05: 13(-2.75,-3.45) 14(-2.25,-3.45) 15(-1.75,-3.45) 16(-1.25,-3.45) 17(-0.75,-3.45) 18(-0.25,-3.45) 19(0.25,-3.45) 20(0.75,-3.45) 21(1.25,-3.45) 22(1.75,-3.45) 23(2.25,-3.45) 24(2.75,-3.45) 37(2.75,3.45) 38(2.25,3.45) 39(1.75,3.45) 40(1.25,3.45) 41(0.75,3.45) 42(0.25,3.45) 43(-0.25,3.45) 44(-0.75,3.45) 45(-1.25,3.45) 46(-1.75,3.45) 47(-2.25,3.45) 48(-2.75,3.45)
  rect 5.3x5.3 smd: 49(0,0)
  silkscreen extent -4.19,3.12 -3.94,3.37, body extent -3.57,-3.57 3.57,3.57, height 1.01
QFN_MPS_MP2316 [mm]
  rect 0.75x0.25 smd: 1(-0.8,1)
  rect 0.7x0.25 smd: 2(-0.8,0.5) 3(-0.8,0) 4(-0.8,-0.5) 5(-0.8,-1) 7(0.8,-1) 8(0.8,-0.5) 9(0.8,0) 10(0.8,0.5) 11(0.8,1)
  rect 0.25x0.7 smd: 6(0,-1.45) 12(0,1.45)
  rect 0.35x0.25 smd: 13(0,0.5) 14(0,0)
  body extent -1,-1.5 1,1.5, height 1.01
RESC0603X33AL [mil]
  rect 12x12 smd mask+2: 1(-10.5,0) 2(10.5,0)
  body extent -12,-6 12,6, height 13
RESC1005X40N [mm]
  rect 0.57x0.62 smd mask+0.05: 1(-0.48,0) 2(0.48,0)
  body extent -0.5,-0.25 0.5,0.25, height 0.4
RESC1609X55N [mm]
  rect 0.9x1 smd mask+0.05: 1(-0.8,0) 2(0.8,0)
  body extent -0.87,-0.48 0.87,0.48, height 0.55
RESC2013X70N [mm]
  rect 1.05x1.4 smd: 1(-0.95,0) 2(0.95,0)
  body extent -1.1,-0.67 1.1,0.68, height 0.7
RESC3225X60N [mm]
  rect 1.1x2.7 smd: 1(-1.5,0) 2(1.5,0)
  body extent -1.7,-1.35 1.7,1.35, height 0.6
SAMTEC_FTSH-105-01-F-DV [mil]
  rect 110x29 smd: 1(-80,100) 2(80,100) 3(-80,50) 4(80,50) 5(-80,0) 6(80,0) 7(-80,-50) 8(80,-50) 9(-80,-100) 10(80,-100)
  body extent -115,-208 115,208, height 325
SAMTEC_SMM-110-02-F-S [mm]
  rect 0.8x2.35 smd: 1(-9,-1.425) 2(-7,1.425) 3(-5,-1.425) 4(-3,1.425) 5(-1,-1.425) 6(1,1.425) 7(3,-1.425) 8(5,1.425) 9(7,-1.425) 10(9,1.425)
  body extent -10,-1 10,1, height 7.37
SOD3716X135N [mm]
  rect 1x0.8 smd: A(-1.8,0) K(1.8,0)
  body extent -1.95,-0.9 1.95,0.9, height 1.36
SODFL1006X43AN12 [mm]
  rect 0.43x0.32 smd: 1(-0.55,0) 2(0.55,0)
  body extent -0.58,-0.33 0.58,0.33, height 0.4
SODFL1006X43N12 [mm]
  rect 0.32x0.43 smd: 1(-0.55,0) 2(0.55,0)
  body extent -0.58,-0.33 0.58,0.33, height 0.4
SOIC127P600X175-8N [mm]
  rect 1.97x0.6 smd mask+0.05: 1(-2.47,1.915) 2(-2.47,0.645) 3(-2.47,-0.625) 4(-2.47,-1.895) 5(2.47,-1.895) 6(2.47,-0.625) 7(2.47,0.645) 8(2.47,1.915)
  silkscreen extent -2.8,2.55 -2.55,2.8, body extent -3.1,-2.48 3.1,2.52, height 1.75
SON50P120X160X60-5T55X91N [mm] "Small Outline No-Lead (SON with Tab), 0.50 mm pitch; 4 pin, 1.20 mm L X 1.60 mm W X 0.60 mm H body"
  rrect52% 0.67x0.27 smd mask+0.051: 1(-0.81,0.25) 2(-0.81,-0.25) 3(0.81,-0.25) 4(0.81,0.25)
  rect 0.55x0.91 smd paste-0.099 mask+0.025: 5(0,0)
  body extent -0.85,-0.6 0.85,0.6, height 0.6
SON95P300X300X80-7N [mm]
  rect 0.4x1 smd: 1(-0.95,-1.4) 2(0,-1.4) 3(0.95,-1.4) 4(0.95,1.4) 5(0,1.4) 6(-0.95,1.4)
  rect 2x1.3 smd: 7(0,0)
  body extent -1.58,-1.58 1.58,1.58, height 0.8
SOP65P640X120-20N [mm]
  rect 1.5x0.45 smd mask+0.05: 1(-2.9,2.925) 2(-2.9,2.275) 3(-2.9,1.625) 4(-2.9,0.975) 5(-2.9,0.325) 6(-2.9,-0.325) 7(-2.9,-0.975) 8(-2.9,-1.625) 9(-2.9,-2.275) 10(-2.9,-2.925) 11(2.9,-2.925) 12(2.9,-2.275) 13(2.9,-1.625) 14(2.9,-0.975) 15(2.9,-0.325) 16(2.9,0.325) 17(2.9,0.975) 18(2.9,1.625) 19(2.9,2.275) 20(2.9,2.925)
  silkscreen extent -3.05,-3.3 1.91,3.81, body extent -3.2,-3.25 3.2,3.25, height 1.2
SOP65P640X120-28N [mm]
  rect 0.45x1.5 smd: 1(-4.225,-2.9) 2(-3.575,-2.9) 3(-2.925,-2.9) 4(-2.275,-2.9) 5(-1.625,-2.9) 6(-0.975,-2.9) 7(-0.325,-2.9) 8(0.325,-2.9) 9(0.975,-2.9) 10(1.625,-2.9) 11(2.275,-2.9) 12(2.925,-2.9) 13(3.575,-2.9) 14(4.225,-2.9) 15(4.225,2.9) 16(3.575,2.9) 17(2.925,2.9) 18(2.275,2.9) 19(1.625,2.9) 20(0.975,2.9) 21(0.325,2.9) 22(-0.325,2.9) 23(-0.975,2.9) 24(-1.625,2.9) 25(-2.275,2.9) 26(-2.925,2.9) 27(-3.575,2.9) 28(-4.225,2.9)
  body extent -4.9,-3.3 4.9,3.3, height 1.21
SOT65P210X100-3AN [mm]
  rect 0.5x1 smd: 1(-0.65,-1.1) 2(0.65,-1.1) 3(0,1.1)
  silkscreen extent -1.5,-1.25 -1.25,-1, body extent -1.2,-1.12 1.2,1.12, height 1
SOT65P210X110-5N [mm]
  rect 0.4x0.95 smd: 1(-0.65,-1.1) 2(0,-1.1) 3(0.65,-1.1) 4(0.65,1.1) 5(-0.65,1.1)
  silkscreen extent -1.4,-1.1 -1.2,-0.9, body extent -1.07,-1.2 1.07,1.2, height 1.11
SOT65P210X110-6N [mm]
  rect 0.4x0.95 smd mask+0.05: 1(-0.65,-1.1) 2(0,-1.1) 3(0.65,-1.1) 4(0.65,1.1) 5(0,1.1) 6(-0.65,1.1)
  silkscreen extent -1.4,-1.1 -1.2,-0.9, body extent -1.07,-1.2 1.07,1.2, height 1.11
SOT95P240X110-3N [mm]
  rect 0.7x1.1 smd: 1(-0.95,-1.2) 2(0.95,-1.2) 3(0,1.2)
  body extent -1.56,-1.35 1.56,1.35, height 1.11
SOT95P240X110_GSD-3N [mm]
  rect 0.65x1.05 smd: D(0,1.15) G(-0.95,-1.15) S(0.95,-1.15)
  silkscreen extent -1.78,-1.43 -1.68,-1.32, body extent -1.46,-1.2 1.46,1.2, height 1.1
SOT95P280X145-5N [mm]
  rect 0.6x1.1 smd mask+0.05: 1(-0.95,-1.3) 2(0,-1.3) 3(0.95,-1.3) 4(0.95,1.3) 5(-0.95,1.3)
  silkscreen extent -1.78,-1.43 -1.68,-1.32, body extent -1.53,-1.5 1.53,1.5, height 1.46
SOTFL50P160X60-6N [mm]
  rrect53% 0.56x0.3 smd mask+0.05: 1(-0.78,0.5) 2(-0.78,0) 3(-0.78,-0.5) 4(0.78,-0.5) 5(0.78,0) 6(0.78,0.5)
  silkscreen extent -1.35,0.9 -1.15,1.1, body extent -0.8,-0.8 0.8,0.8, height 0.6
SOTFL50P160X80_GSD-3N [mm]
  rect 0.4x0.77 smd: D(0,0.69) G(-0.5,-0.69) S(0.5,-0.69)
  body extent -0.85,-0.85 0.85,0.85, height 0.8
SW_KSC221J [mm]
  rect 1x2.8 smd: 1(2,2.9) 2(2,-2.9) 3(-2,2.9) 4(-2,-2.9)
  body extent -3.1,-3.4 3.1,3.4, height 3.5
SW_TDA02 [mm]
  rect 1.27x0.76 smd: 1(-3.81,0.635) 2(-3.81,-0.635) 3(3.81,-0.635) 4(3.81,0.635)
  body extent -3.12,-1.84 3.13,1.84, height 2.3
TC_TC2050-IDC-NL [mil]
  round 31 smd paste-50: 1(-100,-25) 2(-50,-25) 3(0,-25) 4(50,-25) 5(100,-25) 6(100,25) 7(50,25) 8(0,25) 9(-50,25) 10(-100,25)
  round 59 hole 39 unplated mask+0: MT1(-150,0) MT2(150,40) MT3(150,-40)
TE_640456-2 [mm] "CONN HEADER VERT 2POS .100 TIN"
  round 1.5 hole 1.02: 1(-1.27,0) 2(1.27,0)
  body extent -2.54,-2.71 2.54,3.13, height 10.03
TP0762 [mil] "30mil SMT Round Testpoint"
  round 30 smd paste-100: 1(0,0)
XMULTIPLE_XMG-9799-8821 [mil]
  round 60 hole 35: 1(50,250)
  round 60 hole 35.43: 2(100,350) 3(150,250) 4(200,350) 5(250,250) 6(300,350) 7(350,250) 8(400,350)
  round 66 hole 40: 9(-24.02,-192.91) 10(75.98,-133.07) 11(374.02,-192.91) 12(474.02,-133.07)
  round 125 hole 126 unplated: MNT1(0,0) MNT2(450,0)
  round 100 hole 63: SHLD1(-80,120) SHLD2(530,120)
  body extent -102,-432 552,409, height 534
XTAL_C3E-3427 [mm]
  rect 1.4x1.15 smd: 1(-1.1,-0.8) 2(1.1,-0.8) 3(1.1,0.8) 4(-1.1,0.8)
  body extent -1.7,-1.35 1.7,1.35, height 0.75

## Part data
C1 C9 C34 C35 C36: library part 1001196, "CAP TANT 100UF 6.3V 20% 1206"
C2 C11 C12 C67 C69 C71 C72: library part 1001168, "CAP CER 10UF 10V 20% X5R 0402"
C3 C18 C19 C41 C53 C62 C65 C88 C90 C92 C93 C94 C95 C97 C102 C103 C155: library part 1001167, "CAP CER 1UF 10V 10% X5R 0402"
C4 C5 C6 C10 C13 C14 C16 C17 C20 C21 C22 C23 C25 C27 C28 C30 C31 C32 C33 C37 C38 C39 C44 C45 C46 C48 C49 C50 C51 C59 C60 C66 C68 C70 C73 C74 C75 C76 C77 C78 C79 C81 C82 C83 C84 C85 C99 C100 C101 C104 C105 C107 C122 C124 C125 C127 C128 C144 C145 C146 C150 C151 C152 C153 C156 C157: library part 1000006, "CAP 100nF 16V 10% X7R 0402"
C7 C126: library part 1000972, "CAP CER 4.7UF 6.3V 20% X5R 0402"
C8 C112: library part 1000998, "CAP CER 22UF 10V 20% X5R 0603"
C15 C40 C43 C52 C58: library part 1000500, "CAP CER 4.7UF 25V 10% X5R 0805"
C24 C26 C149 C154 C158: library part 1000067, "CAP CER 1000PF 50V 10% X7R 0402"
C29 C47: library part 1001024, "CAP CER 0.022UF 100V X7R 0603"
C42 C54 C55: library part 1001576, "CAP CER 470PF 50V 5% NP0 0402"
C56 C57 C111: library part 1000501, "CAP CER 47UF 6.3V 20% X5R 0805"
C61: library part 1001848, "CAP CER 0.3PF 25V NP0 0201 +/-0.1pF"
C63 C64: library part 1000010, "CAP 33pF 50V 5% NP0 0402"
C80: library part 1001847, "CAP CER 0.1PF 25V NP0 0201 +/-0.05pF"
C86 C106 C120 C129 C131 C132 C133 C135 C136 C141 C142: library part 1000073, "CAP CER 1UF 6.3V 20% X5R 0402"
C87 C89 C113: library part 1000918, "CAP CER 0.1UF 50V 10% X7R 0402"
C91 C98 C115 C116 C117 C119: library part 1000111, "CAP CER 10UF 16V 10% X5R 0805"
C96: library part 1000970, "CAP CER 2.2UF 6.3V 20% X5R 0402"
C108: library part 1000007, "CAP 47pF 50V 5% NP0 0402"
C109: library part 1000110, "CAP CER 1UF 25V 10% X5R 0603"
C110 C121: library part 1000512, "CAP CER 0.015UF 16V 10% X7R 0402"
C114: library part 1000566, "CAP CER 100UF 10V 20% X5R 1206"
C118 C130: library part 1001303, "CAP CER 2.2UF 16V 10% X5R 0603"
C134 C137 C138 C139 C140 C143: library part 1001541, "CAP CER 10PF 50V 5% NP0 0402"
C147: library part 1001679, "CAP CER 6.8PF 50V NP0 0402"
CAD1 CAD2 CAD3: library part CAD0066, "CBL PLUG-OF-NAILS 10-PIN"
D1 D3 D4 D11: library part 1001189, "LED GREEN 573NM 1208 SMD"
D2: library part 1001494, "DIODE ZENER 5.1V 500MW SOD123"
D6 D7: library part 1001637, "TVS DIODE 3.3VWM SOD923"
D10: library part 1001264, "TVS DIODE 5VWM SOD923"
D12: library part 1001188, "LED YELLOW 588NM 1208 SMD"
D13 D14: library part 1000794, "DIODE SCHOTTKY 30V 200MA SOT323"
FIDUCIAL1 FIDUCIAL2 FIDUCIAL3 FIDUCIAL4 FIDUCIAL5 FIDUCIAL6 FIDUCIAL7 FIDUCIAL8 FIDUCIAL9 FIDUCIAL10 FIDUCIAL11 FIDUCIAL12: library part CAD0023, "40 Mil Round Fiducial"
FIL1: library part 1001918, "DNF 2 MHZ -1000 MHZ SMD"
H1 H2 H3 H4: library part CAD0006, "NPTH for Tooling, 0.125in dia."
J1: library part 1001105, "DC Power Jack"
J2 J4 J5 J36: library part 1001136, "CONN HEADER 2POS 1.25MM VERT TIN"
J3 J25: library part 1001183, "CONN HEADER 3POS 1.25MM VERT TIN"
J6 J8: library part 1001971, "CONN, RJ45 100BASE-T R/A, -40/85C"
J7: library part 1001118, "CONN TRANSFLSH R/A PUSH-PUSH SMD"
J9: library part 1001137, "CONN HEADER 4POS 1.25MM VERT TIN"
J10: library part 1001128, "CONN HEADER 2POS .100\" SGL GOLD"
J11 J37: library part 1000034, "CONN HEADER 10POS DUAL .05\" SMD"
J12: library part 1001130, "SMCONN,MINI PCI EXP, 6.8MM HT"
J13 J20 J29 J30: library part 1001140, "CONN HEADER 14POS 1.25MM STR TIN"
J14: library part 1001120, "MEMORY CARD 6POS PUSH/PULL SMD"
J15: library part 1001121, "USB Stacked Dual A type"
J16: library part 1001117, "CONN RECEPT MICRO-USB TYPE AB R/A"
J17: library part 1001145, "CONN FPC 20POS 0.5MM PITCH SMD"
J18: library part 1002018, "CONN MMCX JACK STR 50 OHM SMD"
J19 J27 J28 J32 J33: library part 1001138, "CONN HEADER 6POS 1.25MM VERT TIN"
J21: library part 1001144, "CONN FPC 40POS 0.5MM PITCH SMD"
J22: library part 1001133, "CONN JACK STEREO 5POS 3.5MM SMD"
J23 J24: library part 1001495, "CONN RCPT 2MM 10POS SMD"
J26 J34: library part 1001139, "CONN HEADER 8POS 1.25MM VERT TIN"
J31: library part 1001132, "CONN HEADER 20POS 1.25MM R/A SMD"
J35: library part 1002003, "CONN HEADER VERT 2POS .100 TIN"
L1: library part 1001912, "FIXED IND 1.5UH 4.5A 42 MOHM SMD"
L2 L3 L6 L7 L9 L12 L13 L15 L17 L18 L28 L29 L34: library part 1001174, "FERRITE BEAD 220 OHM 2.0A 0805"
L4: library part 1001850, "FIXED IND 0.6NH 850MA 70 MOHM +/-0.1nH"
L5 L30 L31 L32 L33: library part 1001014, "CHOKE COIL COMMON MODE 150MA SMD"
L8 L10 L11 L14 L16: library part 1001173, "CHOKE COM MODE 120 OHM .37A"
L19 L20 L21 L22 L23 L24: library part 1002041, "FERRITE BEAD 1.8 KOHM 0402 1LN"
LBL1: library part 1002170, "LBL,Poly White Blank 0.40x0.40"
NT1: library part CAD0044, "NET TIE FOR I.MX6x SOM"
Q1: library part 1001204, "TRANS GP SS PNP 40V SOT23"
Q2 Q4 Q5 Q6 Q7 Q9 Q10 Q11: library part 1000715, "MOSFET N-CH 60V 115MA SOT-523F"
R1 R2 R21 R27 R39 R48 R79 R82 R206 R223 R225 R226 R250: library part 1000208, "RES 0.0 OHM 1/10W 0603"
R3 R4 R9 R10 R15 R16 R18 R19 R41 R42 R77 R80 R81 R84 R89 R94 R95 R96 R98 R99 R101 R102 R103 R105 R106 R107 R108 R111 R114 R115 R118 R123 R125 R129 R130 R131 R134 R135 R136 R141 R149 R150 R151 R152 R155 R167 R181 R182 R183 R184 R187 R188 R189 R190 R191 R192 R193 R194 R195 R197 R198 R199 R200 R201 R203 R204 R205 R207 R208 R209 R210 R211 R214 R215 R216 R217 R218 R219 R220 R221 R227 R228 R229 R230 R243 R244 R245 R246 R248 R249 R253 R255 R256 R258 R259 R263 R264 R268 R269 R274 R275 R276 R277 R278 R282: library part 1000076, "RES 0.0 OHM 1/10W 0402 SMD"
R5: library part 1000265, "RES 0.0 OHM 1/20W 0201 SMD"
R6 R148 R224 R261 R279 R280: library part 1001557, "RES 0.0 OHM 1/8W JUMP 0805 SMD"
R7 R13 R17 R24 R25 R26 R28 R29 R31 R32 R33 R34 R36 R38 R40 R64 R65 R66 R72 R78 R90 R93 R100 R112 R113 R117 R121 R122 R126 R127 R128 R145 R146 R147 R153 R156 R166 R168 R169 R170 R171 R172 R173 R174 R175 R176 R177 R178 R185 R202 R222 R231 R232 R233 R234 R235 R236 R237 R238 R239 R240 R241 R242 R251 R254 R260 R262 R266 R281: library part 1000537, "RES 10.0K OHM 1/10W 1% 0402 SMD"
R8 R35: library part 1000467, "RES 100 OHM 1/10W 1% 0402 SMD"
R11: library part 1001323, "RES 270 OHM 1/2W 5% 0805 SMD"
R12: library part 1001154, "RES 220 OHM 1/16W 1% 0402 SMD"
R14 R137 R138: library part 1000701, "RES 470K OHM 1/10W 1% 0402 SMD"
R20 R23 R104 R116 R119 R133: library part 1001158, "RES 120 OHM 1/16W 1% 0402 SMD"
R22 R51 R69 R83 R97 R132 R139 R140 R186 R252: library part 1000480, "RES 100K OHM 1/10W 1% 0402 SMD"
R30: library part 1001149, "RES 22.1K OHM 1/16W 1% 0402 SMD"
R37 R53 R56 R57 R58 R59 R60 R61 R62 R63 R75 R154 R158 R159 R160 R161 R162 R163 R164 R165 R247 R265: library part 1000038, "RES 4.7K OHM 1/10W 5% 0402 SMD"
R43 R52 R76 R124: library part 1000465, "RES 150 OHM 1/10W 1% 0402 SMD"
R44 R45 R46 R47 R85 R86 R87 R88: library part 1000466, "RES 49.9 OHM 1/10W 1% 0402 SMD"
R49 R50 R120 R267 R270 R271 R272 R273 R283: library part 1000079, "RES 1.00K OHM 1/10W 1% 0402 SMD"
R54 R70 R157: library part 1000828, "RES 12.1K OHM 1/10W 1% 0402 SMD"
R55: library part 1000229, "RES 0.0 OHM 1/2W 1210 SMD"
R67: library part 1000971, "RES 1.00M OHM 1/16W 1% 0402 SMD"
R68 R71 R73 R74: library part 1001155, "RES 47.0K OHM 1/16W 1% 0402 SMD"
R91: library part 1001153, "RES 27.0K OHM 1/16W 1% 0402 SMD"
R92 R144 R179: library part 1001200, "RES 12.0K OHM 1/10W 1% 0603 SMD"
R109 R110 R196: library part 1001156, "RES 2.20K OHM 1/16W 1% 0402 SMD"
R142: library part 1001916, "RES SMD 2 OHM 5% 1/10W 0603"
R143: library part 1001518, "RES 53.6K OHM 1/10W 1% 0603 SMD"
R180: library part 1000142, "RES 20K OHM 1/10W 5% 0603 SMD"
R212: library part 1001917, "RES SMD 2.2M OHM 5% 1/10W 0402"
R213: library part 1001150, "RES 316K OHM 1/10W 1% 0603 SMD"
R257: library part 1002118, "RES SMD 33K OHM 1% 1/16W 0402"
SW1 SW2: library part 1001124, "SWITCH TACTILE SPST-NO 0.05A 32V"
SW4: library part 1001500, "SWITCH DIP 2POS HALF PITCH 24V"
TP1 TP2 TP3 TP4 TP5 TP8 TP9 TP10 TP11 TP12 TP13 TP14 TP15 TP16: library part CAD0011, "TEST POINT 30mil PAD SMT"
U1 U3: library part 1001972, "MOSFET P-CH 12V 12A 6QFN"
U2: library part 1000965, "eMMC 4GB, -25/85°C, 153FBGA"
U4 U8 U15 U22 U32 U35: library part 1001163, "MOSFET P-CH 20V 3.7A SOT23-3"
U5: library part 1001206, "TVS DIODE 5VWM 9.2VC SMB"
U6: library part 1002001, "IC CODEC AUDIO FLEXSOUND 56TQFN"
U7: library part 1001857, "IC SW W/CTRL SLEW RATE 4TDFN"
U9: library part 1001499, "IC RS232 3V-5.5V DRVR 28-TSSOP"
U10: library part 1001647, "IC LOGIC GATE UNIV 2INPUT SC70-6"
U11: library part 1001973, "ConnectCore for i.MX6UL module - LGA"
U12 U14: library part 1001143, "IC SW DISTRIBUTION 2CHAN 8SOIC"
U13: library part 1001114, "4-PORT USB 2.0 HUB CTRLR 36VQFN"
U16 U24: library part 1001970, "TXRX ETHERNET 10/100 24VQFN"
U17 U26: library part 1001979, "IC REG LDO ADJ 0.15A SOT25"
U18 U19: library part 1001129, "IC CAN TRANSCEIVER 3.3V 8-SOIC"
U20 U21: library part 1001265, "TVS DIODE 5.5VWM 6SON"
U23: library part 1001907, "IC REG BUCK ADJ 3A SYNC"
U25: library part 1001994, "SMIC, 27-bit LVDS dual-out transmitter"
U27: library part 1002077, "KINETIS KL14, 32FL/4SR, -40/+105°C, QFN48"
U28: library part 1002006, "IC SMART TAG , 2KB"
U30: library part 1001160, "IC GATE NAND 2-INP HS LOG SC70-5"
U31: library part 1001368, "IC SWITCH BUS 8BIT FET 20-TSSOP"
U33 U34: library part 1001179, "IC SWITCH SPDT SC88"
U36: library part 1001009, "MOSFET DL N-CH 60V 410MA SOT-563"
X2: library part 1001134, "CRYSTAL 24MHZ 18PF SMD"

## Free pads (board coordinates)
  rect 5.8x5.8 / inner rect 0x0 / far side rect 5.8x5.8 hole 2.6: 0(8.7,22.15) 0(8.7,46.35) 0(32.85,22.15)
  round 5.5 hole 3.2: TOOL1(3,3) TOOL2(97,3) TOOL3(97,69) TOOL4(3,69)

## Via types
v1: diameter 0.56, hole 0.25, Top to Bottom, tented both sides, 1002 vias
v2: diameter 0.46, hole 0.2, Top to Bottom, tented both sides, 468 vias
v3: diameter 0.457, hole 0.2, Top to Bottom, tented both sides, 132 vias

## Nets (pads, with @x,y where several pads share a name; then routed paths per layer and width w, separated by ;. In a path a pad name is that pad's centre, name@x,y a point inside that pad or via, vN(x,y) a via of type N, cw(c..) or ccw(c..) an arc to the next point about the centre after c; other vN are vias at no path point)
1V8_CODEC: C91.2 C92.1 C93.1 C94.1 C118.2 R91.2 U6.25 U6.50 U6.53 U17.5 | length 33.2
  Top w0.25: U17.5@74.758,18.5 73.97,18.5 R91.2@73.4,19.07 72.34,19.07 C118.2@72.17,18.9 72.17,17.53 C91.2@72.5,17.2 73.6,17.2 74.15,16.65 v2(74.85,16.65)
  Signal_4 w0.5: v2(74.85,16.65) 74.85,20.25 78.6,24 78.6,27.229 79.571,28.2 v2(80.5,28.2)
  Bottom w0.125: v2(74.85,16.65) 74.9,16.6 74.9,16.94 C92.1@74.54,17.3 74.54,17.348 75.334,18.142 75.334,18.32 75.38,18.366 75.38,18.88 U6.25@75.4,18.88 ; U6.50@77,25.74 76.982,25.758 76.982,26.873 77.555,27.446 78.071,27.446 78.117,27.4 78.3,27.4 78.5,27.6 C93.1@78.5,28.04 C94.1@79.7,28.04 ; U6.53@78.2,25.74 78.2,26.309 78.418,26.527 78.418,26.618 78.8,27 79.1,27 79.7,27.6 C94.1@79.7,28.04 ; v2(80.5,28.2) 80.34,28.04 C94.1@79.7,28.04
3V3: C12.2 C13.2 C27.2 C60.1 C99.2 C100.2 C151.1 C153.2 C156.2 C157.2 CAD3.1 D14.1 J4.1 J7.4 J9.3 J17.20 J21.38 J28.3 J29.5 J31.1 J34.1 J37.1 L28.1 R4.2 R7.1 R17.2 R22.1 R27.1 R30.2 R31.2 R32.2 R33.2 R34.2 R39.1 R40.1 R42.1 R49.1 R50.1 R51.1 R53.2 R64.2 R69.1 R75.1 R78.1 R82.1 R93.1 R100.2 R109.2 R110.2 R117.1 R121.2 R122.1 R127.1 R128.1 R132.1 R135.2 R139.1 R154.2 R168.1 R169.2 R170.2 R171.2 R172.2 R173.2 R185.1 R186.1 R206.1 R222.2 R223.1 R233.2 R234.2 R235.2 R236.2 R237.2 R240.1 R252.1 R254.1 R266.1 R268.1 R280.1 R281.1 U4.S U8.S U9.23 U9.26 U18.3 U19.3 U22.S U25.D9 U25.E7 U25.E9 U25.G7 U30.5 U31.20 U32.S U33.5 U34.5 U36.2 U36.5 | length 175
  Top w0.125: U25.D9@39.65,61.75 v2(39.975,62.075) U25.E9@40.3,61.75 ; U25.E7@40.3,60.45 v3(40.95,59.8) U25.G7@41.6,60.45
  Top w0.25: R268.1@4.328,26.908 v2(4.328,27.5) ; v2(7.8,29.2) 7.8,27.128 J37.1@7.96,26.968 ; U30.5@11.3,38.15 11.65,38.15 11.86,38.36 12.75,38.36 12.7,38.41 v1(12.7,39) ; 14.476,65.8 J21.38@14.476,67.05 ; v1(16.9,55.7) 16.9,55.4 16.8,55.3 L28.1@17.25,54.85 ; v1(28.367,38.98) 28.44,38.907 28.553,38.907 28.534,38.925 U9.23@30.15,38.925 ; v2(29,32.6) 29.22,32.6 R64.2@29.62,32.2 ; U9.26@30.15,40.875 31.017,40.875 C27.2@31.792,40.1 ; R127.1@31.9,39.08 31.9,39.992 C27.2@31.792,40.1 ; v1(32.3,41.2) 32.3,40.64 31.948,40.288 C27.2@31.948,40.1 C27.2@31.792,40.1 ; v2(33,50.25) 33.46,50.25 33.425,50.285 U31.20@33.425,51.85 ; R266.1@37,64.98 v1(37,65.75) ; R171.2@37,66.62 v1(37,65.75) ; v1(37.75,37.25) R135.2@37.75,38.02 ; R172.2@38.1,64.98 38.1,65.629 37.98,65.75 v1(37,65.75) ; v1(38.4,30.3) R75.1@39.12,30.3 ; R173.2@39.1,53.42 39.2,53.32 v2(39.2,52.6) ; v1(41.7,48) 44.9,48 v2(45.2,48.3) ; v2(44.5,52.5) R235.2@45.92,52.5 R234.2@45.92,53.7 ; v1(45.1,62.2) v1@45.156,62.2 ; D14.1@45.15,66.6 45.1,66.65 45.1,67.3 v1(45.4,67.6) ; v1(45.8,46.9) 45.92,47.02 R236.2@45.92,48.3 v2(45.2,48.3) ; R17.2@45.92,49.6 45.4,49.6 45.2,49.4 v2(45.2,48.3) ; R233.2@45.92,56.7 45.4,56.7 45,57.1 v3(45,57.3) 45,57.5 45.4,57.9 R222.2@45.92,57.9 ; R100.2@45.92,60.7 45.156,61.464 v1@45.156,62.2 ; R237.2@45.92,61.9 45.62,62.2 v1@45.156,62.2 ; v1(47.268,39.346) 48.872,40.95 R280.1@50.65,40.95 ; J17.20@49,66.8 v1(49,68.547) ; v1(51.95,21.25) 52.65,21.95 54.23,21.95 R121.2@55.25,22.97 ; R121.2@55.1,23.12 R121.2@55.25,22.97 ; R254.1@57.6,33.12 57.6,32.85 v3(57.9,32.55) ; U36.5@59.18,22.9 U36.2@57.62,22.9 55.32,22.9 R121.2@55.25,22.97 ; R109.2@69,22.52 70.18,22.52 ; R110.2@69,25.73 69.77,25.73 70.18,25.32 70.18,22.52 ; R32.2@69.75,15.46 R31.2@71,15.46 R30.2@72.25,15.46 ; C12.2@73.5,14.52 73.5,14.4 74.1,13.8 v2(74.1,13.7) 74.75,14.35 C13.2@74.75,14.52 ; R132.1@74.12,22.8 72.3,22.8 v2(71.1,21.6) 70.18,22.52 ; R122.1@77.23,66.5 77.73,67 v1(78,67) ; R34.2@77.25,15.48 77.25,16.05 77.5,16.3 77.6,16.2 v2(78,16.2) 78.2,16.2 78.3,16.3 78.5,16.1 R33.2@78.5,15.48 ; U33.5@78.7,59.1 79.74,59.1 C156.2@79.8,59.16 v1(79.8,59.9) ; U34.5@78.7,62.8 79.86,62.8 C157.2@79.9,62.84 v1(79.9,62.1) ; R128.1@80.738,21.25 81.208,21.72 U22.S@81.208,22.6 81.226,22.618 R206.1@83.1,22.618 83.1,21.9 83.25,21.75 83.3,21.8 v1(84.3,21.8) ; R117.1@81.68,67.75 v1(82.5,67.75) ; v1(84.2,66.25) 84.5,66.55 R281.1@86.27,66.55
  Top w0.5: 14.476,65.8 14.476,64.306 14.443,64.272 14.443,63.457 14.7,63.2 v2(15,63.2)
  Signal_4 w0.25: v1(38.4,30.3) 39.1,29.6 43.35,29.6 43.977,30.227 v1(43.977,30.276) ; v1(54.4,58.3) 55.5,57.2 v2(60.1,57.2)
  Signal_4 w0.5: v1(30.7,62.8) 34.05,62.8 v1(37,65.75)
  Signal_4 w0.7: J28.3@78.75,70 78.75,68.459 79.459,67.75 v1(82.5,67.75)
  Bottom w0.25: v1(10.5,65.2) J31.1@11.351,65.2 ; CAD3.1@13.04,27.115 13.855,26.3 v2(15.3,26.3) ; R4.2@14.23,22.5 14.23,23.23 14.75,23.75 v1(15.5,23.75) ; R7.1@16.725,36.23 v1(16.725,36.9) 17.875,36.9 U8.S@18.075,36.7 ; R51.1@16.75,39.48 v1(16.75,40.15) ; R27.1@21.3,39 v1(21.3,39.7) ; v2(25.6,58.9) 25.6,57.958 26.008,57.55 27,57.55 27.83,56.72 R252.1@28.5,56.72 ; R49.1@28.25,32.98 28.82,32.98 28.835,32.965 29,32.8 v2(29,32.6) ; R53.2@28.98,29.5 29,29.52 28.7,29.82 v2(28.7,30.1) 28.7,30.43 29,30.73 R50.1@28.98,30.75 ; R154.2@28.98,49 29.051,49.071 v2(29.051,49.577) ; v1(30.7,62.8) R168.1@31.32,62.8 ; R169.2@39.6,62.754 39.975,62.379 v2(39.975,62.075) 40.495,62.075 R170.2@40.52,62.1 ; C60.1@40.76,60.6 40.76,59.99 v3(40.95,59.8) ; R69.1@40.93,48 v1(41.7,48) ; U32.S@44.249,46.539 44.249,47.251 43.93,47.57 R240.1@43.93,48 44.9,48 v2(45.2,48.3) ; R139.1@53.75,57.63 54.4,58.28 v1(54.4,58.3) ; R186.1@68.6,57.68 v1(68.6,58.5) 69.1,59 R223.1@69.7,59 ; R78.1@70.48,53.5 70.532,53.552 70.532,55.432 v1(70.8,55.7) R42.1@71.6,55.7 ; v2(74.1,13.7) 74.1,11.5 75.8,9.8 J7.4@75.8,5.125 ; U4.S@76.32,57.97 77.762,57.97 78.38,58.588 R185.1@78.38,59.9 v1(79.8,59.9) ; R40.1@82.95,65.02 83,64.97 v1(83,64.4) ; U18.3@86.125,60.03 86.125,58.215 86.1,58.19 86.531,57.759 v2(86.531,57.338) 86.531,56.869 86.8,56.6 89.6,56.6 91.1,58.1 C100.2@91.69,58.1 91.69,59.965 U19.3@91.625,60.03 ; R93.1@86.58,26.9 86.78,26.7 v1(87.2,26.7) ; R22.1@91.1,24.88 v1(91.1,25.6)
  Bottom w0.5: v1(45.8,46.9) 45.8,46 R82.1@45.9,45.9 ; v1(75.5,56.7) 75.5,56.5 R39.1@76.4,56.5
  other v2: 71.625,15.46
